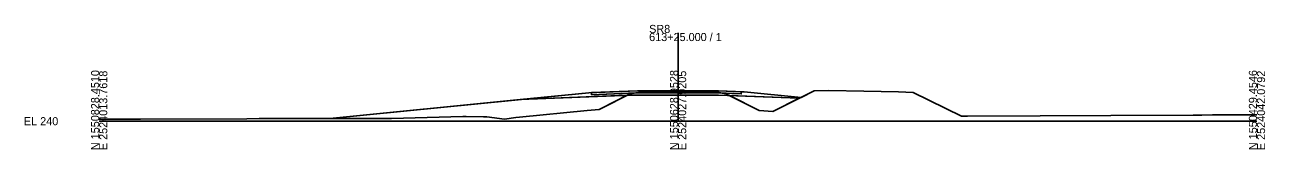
# Model space of a CAD drawing. Extents: x -26 to 2803, y -10 to 19537.
# Drawn here: x 2374.3 to 2802.8, y -9.7 to 33.4 of the extents above; entities that cross this region are included whole.
import ezdxf

# ---------------------------------------------------------------- set-up
doc = ezdxf.new("R2010")
doc.units = 0
for name, color, linetype in [('1', 7, 'Continuous'), ('Draft_XS_Text', 7, 'Continuous'), ('DTM_P_SUBGRADE_1', 7, 'Continuous'), ('DTM_X_GROUND', 7, 'Continuous'), ('SLOPE_STAKES_FILL', 7, 'Continuous'), ('XS_P_ASPHALT', 7, 'Continuous'), ('XS_P_SHOULDER', 7, 'Continuous')]:
    doc.layers.add(name, color=color, linetype=linetype)

msp = doc.modelspace()

# ---------------------------------------------------------------- linework, layer by layer
at = {"layer": '1'}
for p, q in [((2600, 0), (2600, 30.52)), ((2400, 0), (2600, 0)), ((2600, 0), (2800, 0))]:
    msp.add_line(p, q, dxfattribs=at)
at = {"layer": 'Draft_XS_Text'}
for p, q in [((2632.77, 3.41), (2646.99, 10.46)), ((2646.99, 10.46), (2652.03, 10.66)), ((2652.03, 10.66), (2664.12, 10.42)), ((2664.12, 10.42), (2676.21, 10.18)), ((2676.21, 10.18), (2681.25, 9.98)), ((2681.25, 9.98), (2697.94, 1.7))]:
    msp.add_line(p, q, dxfattribs=at)
for points in [[(2400, 0.69), (2414.24, 0.74), (2450.98, 0.87), (2455.22, 0.88), (2478.22, 0.92), (2497.45, 0.96), (2500.98, 0.96), (2525.61, 1.63), (2526.81, 1.66), (2532.79, 1.57), (2533.89, 1.56), (2540.02, 0.71), (2543.9, 1.24), (2545.24, 1.43), (2568.56, 3.69), (2572.77, 4.1), (2573.42, 4.43), (2583.48, 9.51), (2586.38, 9.9), (2600, 10.17), (2600.43, 10.17), (2614.23, 9.92), (2616.59, 9.5), (2616.98, 9.29), (2628, 3.65), (2632.77, 3.41)], [(2697.94, 1.7), (2700.02, 1.73), (2725.06, 1.88), (2749.46, 2), (2777.96, 2.13), (2780.92, 2.14), (2784.6, 2.15), (2789.32, 2.17), (2795.61, 2.19), (2800, 2.21)]]:
    msp.add_lwpolyline(points, dxfattribs=at)
at = {"layer": 'DTM_P_SUBGRADE_1'}
for p, q in [((2584, 9.04), (2545.46, 7.5)), ((2586, 9.04), (2584, 9.04)), ((2600, 9.04), (2586, 9.04)), ((2600, 9.04), (2614, 9.04)), ((2614, 9.04), (2641.87, 7.92)), ((2641.87, 7.92), (2642.47, 8.22))]:
    msp.add_line(p, q, dxfattribs=at)
at = {"layer": 'DTM_X_GROUND'}
for p, q in [((2569.13, 9.86), (2479.73, 0.92)), ((2586, 10.54), (2569.13, 9.86)), ((2600, 10.54), (2586, 10.54)), ((2600, 10.54), (2614, 10.54)), ((2614, 10.54), (2622.84, 10.18)), ((2622.84, 10.18), (2642.47, 8.22))]:
    msp.add_line(p, q, dxfattribs=at)
at = {"layer": 'SLOPE_STAKES_FILL'}
for p, q in [((2479.73, 0.92), (2569.13, 9.86)), ((2569.13, 9.86), (2586, 10.54)), ((2586, 10.54), (2600, 10.54)), ((2600, 10.54), (2614, 10.54)), ((2614, 10.54), (2622.84, 10.18)), ((2622.84, 10.18), (2642.47, 8.22)), ((2642.47, 8.22), (2646.99, 10.46)), ((2646.99, 10.46), (2652.03, 10.66)), ((2652.03, 10.66), (2664.12, 10.42)), ((2664.12, 10.42), (2676.21, 10.18)), ((2676.21, 10.18), (2681.25, 9.98)), ((2681.25, 9.98), (2697.94, 1.7))]:
    msp.add_line(p, q, dxfattribs=at)
for points in [[(2400, 0.69), (2414.24, 0.74), (2450.98, 0.87), (2455.22, 0.88), (2478.22, 0.92), (2479.73, 0.92)], [(2697.94, 1.7), (2700.02, 1.73), (2725.06, 1.88), (2749.46, 2), (2777.96, 2.13), (2780.92, 2.14), (2784.6, 2.15), (2789.32, 2.17), (2795.61, 2.19), (2800, 2.21)]]:
    msp.add_lwpolyline(points, dxfattribs=at)
at = {"layer": 'XS_P_ASPHALT'}
for p, q in [((2570.13, 9.15), (2570.13, 9.9)), ((2586, 9.79), (2570.13, 9.15)), ((2600, 9.79), (2586, 9.79)), ((2600, 9.79), (2614, 9.79)), ((2614, 9.79), (2621.81, 9.47)), ((2621.81, 9.47), (2621.81, 10.22))]:
    msp.add_line(p, q, dxfattribs=at)
at = {"layer": 'XS_P_SHOULDER'}
for points in [[(2568.56, 3.69), (2572.77, 4.1), (2573.42, 4.43), (2582.43, 8.97), (2545.46, 7.5), (2479.73, 0.92), (2497.45, 0.96), (2500.98, 0.96), (2525.61, 1.63), (2526.81, 1.66), (2532.79, 1.57), (2533.89, 1.56), (2540.02, 0.71), (2543.9, 1.24), (2545.24, 1.43)], [(2583.48, 9.51), (2585.36, 9.76), (2570.13, 9.15), (2570.13, 9.9), (2569.13, 9.86), (2545.46, 7.5), (2582.43, 8.97)], [(2600.43, 10.17), (2614.23, 9.92), (2615.22, 9.74), (2621.81, 9.47), (2621.81, 10.22), (2614, 10.54), (2600, 10.54), (2586, 10.54), (2570.13, 9.9), (2570.13, 9.15), (2585.36, 9.76), (2586.38, 9.9), (2600, 10.17)], [(2614, 9.04), (2617.78, 8.89), (2616.98, 9.29), (2616.59, 9.5), (2615.22, 9.74), (2614, 9.79), (2600, 9.79), (2586, 9.79), (2585.36, 9.76), (2583.48, 9.51), (2582.43, 8.97), (2584, 9.04), (2586, 9.04), (2600, 9.04)], [(2600.43, 10.17), (2614.23, 9.92), (2615.22, 9.74), (2614, 9.79), (2600, 9.79), (2586, 9.79), (2585.36, 9.76), (2586.38, 9.9), (2600, 10.17)], [(2616.98, 9.29), (2617.78, 8.89), (2641.87, 7.92), (2642.47, 8.22), (2622.84, 10.18), (2621.81, 10.22), (2621.81, 9.47), (2615.22, 9.74), (2616.59, 9.5)], [(2628, 3.65), (2632.77, 3.41), (2641.87, 7.92), (2617.78, 8.89)]]:
    msp.add_lwpolyline(points, close=True, dxfattribs=at)

# ---------------------------------------------------------------- texts
at = {"layer": '1'}
for s, p in [('SR8', (2590, 30.52)), ('613+25.000 / 1', (2590, 27.72)), ('EL 240', (2374, -1.4))]:
    msp.add_text(s, height=2.8, dxfattribs=at).set_placement(p)
for s, p in [('N 1550828.4510', (2400, -10)), ('E 2524013.7618', (2402.8, -10)), ('N 1550628.9528', (2600, -10)), ('E 2524027.9205', (2602.8, -10)), ('N 1550429.4546', (2800, -10)), ('E 2524042.0792', (2802.8, -10))]:
    msp.add_text(s, height=2.8, rotation=90, dxfattribs=at).set_placement(p)

doc.saveas('drawing.dxf')
